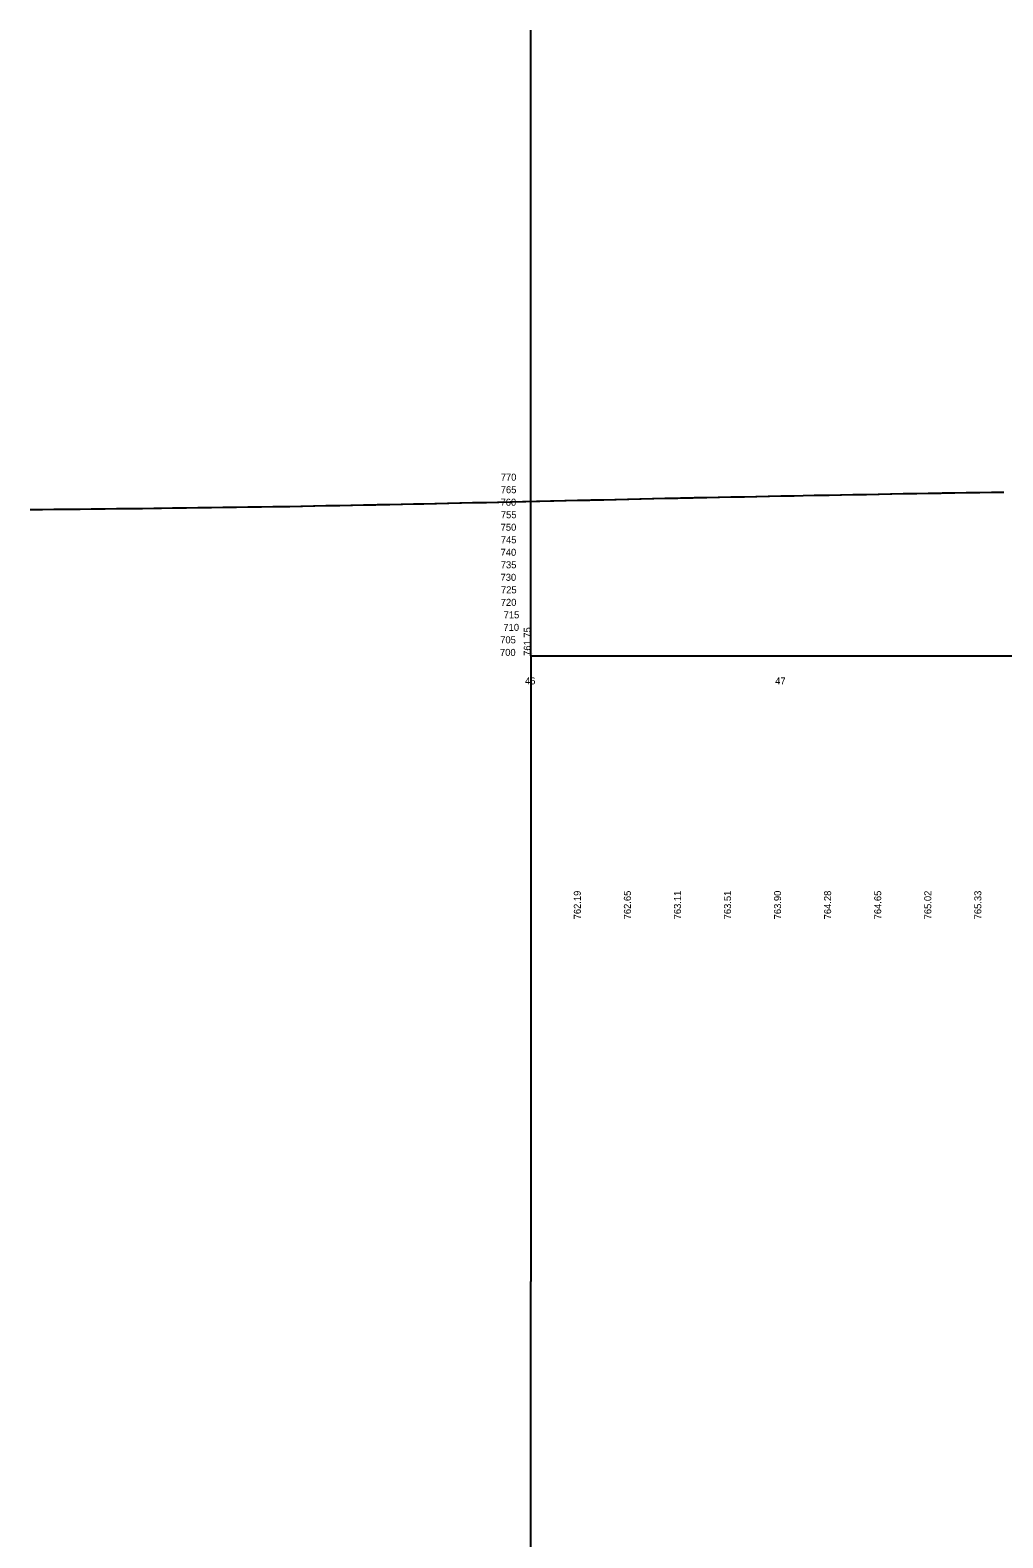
# Model space of a CAD drawing. Extents: x -209 to 3291, y 1080 to 3580.
# Drawn here: x -209 to 180, y 2978 to 3580 of the extents above; entities that cross this region are included whole.
import ezdxf

# ---------------------------------------------------------------- set-up
doc = ezdxf.new("R2010")
doc.units = 0
for name, color, linetype in [('GK_Cells', 7, 'Continuous'), ('PF_P_Sta_Elev_Text', 7, 'Continuous'), ('PF_X_Ground_Line', 7, 'Continuous'), ('PF_X_Text', 7, 'Continuous')]:
    doc.layers.add(name, color=color, linetype=linetype)

msp = doc.modelspace()

# ---------------------------------------------------------------- linework, layer by layer
at = {"layer": 'GK_Cells'}
for p, q in [((-8.74, 3330.13), (-8.74, 3580.13)), ((-8.74, 3330.13), (3291.26, 3330.13)), ((-8.74, 3330.13), (-8.74, 3080.13)), ((-8.74, 2080.13), (-8.74, 3080.13))]:
    msp.add_line(p, q, dxfattribs=at)
at = {"layer": 'PF_X_Ground_Line'}
for points in [[(-208.74, 3388.59), (-204.31, 3388.64), (-203.8, 3388.64), (-199.31, 3388.69), (-198.8, 3388.7), (-194.31, 3388.75), (-193.8, 3388.75), (-189.31, 3388.8), (-188.8, 3388.81), (-184.31, 3388.86), (-183.8, 3388.86), (-179.3, 3388.91), (-178.8, 3388.92), (-174.3, 3388.97), (-173.8, 3388.97), (-169.3, 3389.02), (-168.8, 3389.03), (-164.3, 3389.08), (-163.8, 3389.08), (-159.3, 3389.13), (-158.8, 3389.14), (-156.8, 3389.16), (-156.3, 3389.17), (-151.81, 3389.23), (-151.3, 3389.24), (-146.81, 3389.3), (-146.3, 3389.3), (-141.82, 3389.37), (-141.29, 3389.37), (-136.82, 3389.44), (-136.29, 3389.44), (-131.82, 3389.51), (-131.28, 3389.51), (-126.83, 3389.57), (-126.28, 3389.58), (-121.83, 3389.64), (-121.27, 3389.65), (-116.83, 3389.71), (-116.27, 3389.72), (-111.84, 3389.78), (-111.26, 3389.79), (-106.84, 3389.85), (-106.4, 3389.86), (-105, 3389.88), (-100.59, 3389.96), (-100, 3389.97), (-95.59, 3390.06), (-95.01, 3390.07), (-90.58, 3390.16), (-90.01, 3390.17), (-85.58, 3390.26), (-85.01, 3390.27), (-80.58, 3390.36), (-80.01, 3390.37), (-75.58, 3390.46), (-75.01, 3390.47), (-70.58, 3390.55), (-70.01, 3390.57), (-65.57, 3390.65), (-65.01, 3390.66), (-60.57, 3390.75), (-60.01, 3390.76), (-55.57, 3390.85), (-55.01, 3390.86), (-51.83, 3390.92), (-51.45, 3390.93), (-47.01, 3391.03), (-46.45, 3391.04), (-42.01, 3391.14), (-41.46, 3391.15), (-37.02, 3391.25), (-36.46, 3391.26), (-32.02, 3391.36), (-31.46, 3391.37), (-27.02, 3391.47), (-26.46, 3391.48), (-22.02, 3391.57), (-21.46, 3391.59), (-17.03, 3391.68), (-16.46, 3391.7), (-12.03, 3391.79), (-11.46, 3391.81), (-10.66, 3391.84), (-6.39, 3391.93), (-5.18, 3391.96), (-0.9, 3392.06), (-0.13, 3392.06), (0.43, 3392.07), (4.87, 3392.17), (5.43, 3392.19), (9.87, 3392.29), (10.42, 3392.3), (14.87, 3392.4), (15.41, 3392.42), (19.87, 3392.52), (20.41, 3392.53), (24.86, 3392.64), (25.4, 3392.65), (29.86, 3392.75), (30.39, 3392.76), (34.86, 3392.87)], [(34.86, 3392.87), (35.39, 3392.88), (39.86, 3392.98), (40.38, 3392.99), (44.86, 3393.1), (45.38, 3393.11), (49.86, 3393.21), (50.01, 3393.21), (51.13, 3393.24), (51.64, 3393.25), (56.13, 3393.34), (56.63, 3393.35), (61.13, 3393.44), (61.62, 3393.45), (66.13, 3393.54), (66.61, 3393.55), (71.13, 3393.64), (71.6, 3393.65), (76.13, 3393.73), (76.59, 3393.74), (81.13, 3393.83), (81.58, 3393.84), (86.13, 3393.93), (86.57, 3393.94), (91.13, 3394.03), (91.56, 3394.04), (92.01, 3394.06), (96.48, 3394.14), (100.03, 3394.21), (104.53, 3394.3), (105, 3394.3), (105.42, 3394.3), (110, 3394.39), (110.42, 3394.4), (114.99, 3394.48), (115.43, 3394.49), (119.99, 3394.58), (120.43, 3394.58), (124.99, 3394.67), (125.44, 3394.68), (129.99, 3394.76), (130.44, 3394.77), (134.98, 3394.85), (135.45, 3394.86), (139.98, 3394.95), (140.45, 3394.95), (144.98, 3395.04), (145.46, 3395.05), (149.97, 3395.13), (150.15, 3395.13), (150.71, 3395.14), (155.23, 3395.21), (155.71, 3395.22), (160.23, 3395.29), (160.71, 3395.3), (165.24, 3395.37), (165.71, 3395.38), (170.25, 3395.45), (170.7, 3395.45), (175.26, 3395.52), (175.7, 3395.53), (180.26, 3395.6)]]:
    msp.add_lwpolyline(points, dxfattribs=at)

# ---------------------------------------------------------------- texts
at = {"layer": 'GK_Cells'}
for s, p in [('450', (-8.74, 3331.6)), ('WINCHESTER', (-8.74, 3331.39)), ('4600.000000', (-8.74, 3331.18)), ('700', (-8.74, 3330.97)), ('1', (-8.74, 3330.76)), ('1', (-8.74, 3330.55)), ('NOGAP', (-8.74, 3330.34))]:
    msp.add_text(s, height=0.14, dxfattribs=at).set_placement(p)
at = {"layer": 'PF_P_Sta_Elev_Text'}
for s, p in [('770', (-20.73, 3400.13)), ('770', (-20.73, 3400.13)), ('770', (-20.73, 3400.13)), ('765', (-20.73, 3395.13)), ('765', (-20.73, 3395.13)), ('765', (-20.73, 3395.13)), ('760', (-20.82, 3390.13)), ('760', (-20.82, 3390.13)), ('760', (-20.82, 3390.13)), ('755', (-20.69, 3385.13)), ('755', (-20.69, 3385.13)), ('755', (-20.69, 3385.13)), ('750', (-20.77, 3380.13)), ('750', (-20.77, 3380.13)), ('750', (-20.77, 3380.13)), ('745', (-20.71, 3375.13)), ('745', (-20.71, 3375.13)), ('745', (-20.71, 3375.13)), ('740', (-20.8, 3370.13)), ('740', (-20.8, 3370.13)), ('740', (-20.8, 3370.13)), ('735', (-20.73, 3365.13)), ('735', (-20.73, 3365.13)), ('735', (-20.73, 3365.13)), ('730', (-20.82, 3360.13)), ('730', (-20.82, 3360.13)), ('730', (-20.82, 3360.13)), ('725', (-20.64, 3355.13)), ('725', (-20.64, 3355.13)), ('725', (-20.64, 3355.13)), ('720', (-20.73, 3350.13)), ('720', (-20.73, 3350.13)), ('720', (-20.73, 3350.13)), ('715', (-19.58, 3345.13)), ('715', (-19.58, 3345.13)), ('715', (-19.58, 3345.13)), ('705', (-20.95, 3335.13)), ('705', (-20.95, 3335.13)), ('705', (-20.95, 3335.13)), ('710', (-19.67, 3340.13)), ('710', (-19.67, 3340.13)), ('710', (-19.67, 3340.13)), ('700', (-21.04, 3330.13)), ('700', (-21.04, 3330.13)), ('700', (-21.04, 3330.13)), ('46', (-11.05, 3318.73)), ('47', (88.9, 3318.73))]:
    msp.add_text(s, height=2.8, dxfattribs=at).set_placement(p)
at = {"layer": 'PF_X_Text'}
for s, p in [('761.75', (-8.74, 3330.13)), ('762.19', (11.26, 3224.88)), ('762.65', (31.26, 3224.88)), ('763.11', (51.26, 3224.88)), ('763.51', (71.26, 3224.88)), ('763.90', (91.26, 3224.88)), ('764.28', (111.26, 3224.88)), ('764.65', (131.26, 3224.88)), ('765.02', (151.26, 3224.88)), ('765.33', (171.26, 3224.88))]:
    msp.add_text(s, height=2.8, rotation=90, dxfattribs=at).set_placement(p)

doc.saveas('drawing.dxf')
